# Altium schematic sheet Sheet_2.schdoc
size 299 x 190 mm
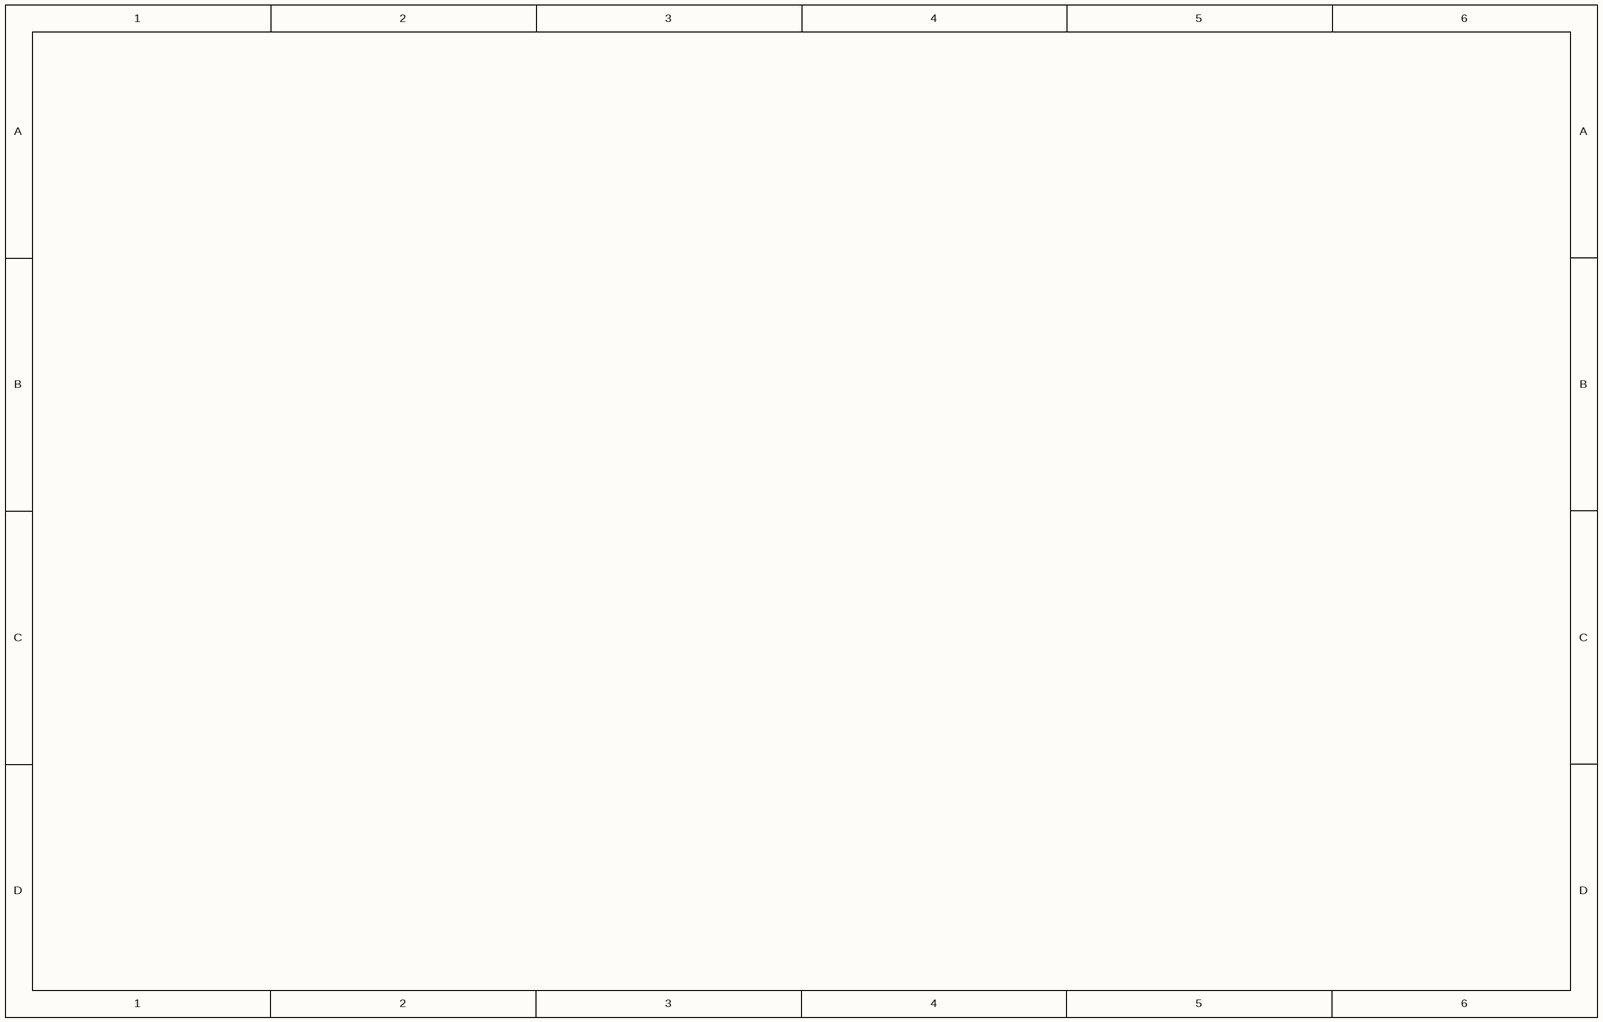
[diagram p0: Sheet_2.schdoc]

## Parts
C6  100nF  [1206]
C7  100nF  [1206]
C8  100nF  [1206]
C9  100nF  [1206]
C15  100nF  [1206]
C17  100nF  [1206]
C18  100nF  [1206]
H1  Header_4*1  [HEADER_4*1]
H2  Header_4*1  [HEADER_4*1]
H3  Header_4*1  [HEADER_4*1]
H4  Header_4*1  [HEADER_4*1]
P1  SMA-KWE  [SMA-KWE]
R6  10K  [R1206]
R7  10K  [R1206]
R8  10K  [R1206]
R10  10K  [R1206]
R11  10K  [R1206]
R12  10K  [R1206]
U2  RA-02  [WIRELM-SMD_RA-02]
U6  HEADER 5*1  [HEADER_6*1]  (value not drawn)
U8  HEADER 5*1  [HEADER_6*1]  (value not drawn)

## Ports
I2C_SCL (in), I2C_SDA (in), LORA_DIO0 (in), LORA_MISO (in), LORA_MOSI (in), LORA_NSS (in), LORA_RST (in), LORA_SCK (in), ULTRA SONIC1_ECHO (in), ULTRA SONIC1_TRIG (in), ULTRA SONIC2_ECHO (in), ULTRA SONIC2_TRIG (in)

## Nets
+3.3V: H1.1 H2.1 H3.1 H4.1 U2.3(3.3V)
+5V: U6.5 U8.5
GND: H1.2 H2.2 H3.2 H4.2 P1.2 P1.3 P1.4 P1.5 R7.2 R11.2 U2.2(GND) U2.9(GND) U2.16(GND) U6.1 U8.1
I2C_SCL: H1.3 H2.3 H3.3 H4.3 ; port I2C_SCL
I2C_SDA: H1.4 H2.4 H3.4 H4.4 ; port I2C_SDA
LORA_DIO0: U2.5(DIO0) ; port LORA_DIO0
LORA_MISO: U2.13(MISO) ; port LORA_MISO
LORA_MOSI: U2.14(MOSI) ; port LORA_MOSI
LORA_NSS: U2.15(NSS) ; port LORA_NSS
LORA_RST: U2.4(RESET) ; port LORA_RST
LORA_SCK: U2.12(SCK) ; port LORA_SCK
ULTRA SONIC1_ECHO: R8.2 R12.1 ; port ULTRA SONIC1_ECHO
ULTRA SONIC1_TRIG: U6.4 ; port ULTRA SONIC1_TRIG
ULTRA SONIC2_ECHO: R6.1 R10.1 ; port ULTRA SONIC2_ECHO
ULTRA SONIC2_TRIG: U8.4 ; port ULTRA SONIC2_TRIG
NetP1_1: P1.1 U2.1(ANT)
NetR6_2: R6.2 R7.1
NetR8_1: R8.1 R11.1
NetR10_2: R10.2 U8.3
NetR12_2: R12.2 U6.3

Not connected (* = marked no-connect by the designer): U2 6(DIO1)* 7(DIO2)* 8(DIO3)* 10(DIO4)* 11(DIO5)*; U6 2*; U8 2*

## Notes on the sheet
- Labels drawn without touching a wire or pin: GND

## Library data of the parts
C6-C9 C15 C17 C18 = 100nF: BOM_Manufacturer: HEC; BOM_Manufacturer Part: C1206X224K251T 3K; nameAlias: Capacitance
H1-H4 = Header_4*1: Contributor: harkhka
P1 = SMA-KWE: BOM_Manufacturer: LCSC
R6-R8 R10-R12 = 10K: BOM_Manufacturer: SANYEAR; BOM_Manufacturer Part: SY1206JN10KP; nameAlias: Resistance (Ohms); Contributor: LCSC
U2 = RA-02: BOM_Manufacturer: Ai-Thinker; Contributor: LCSC
U6 U8 = HEADER 5*1: Contributor: mhmd2c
